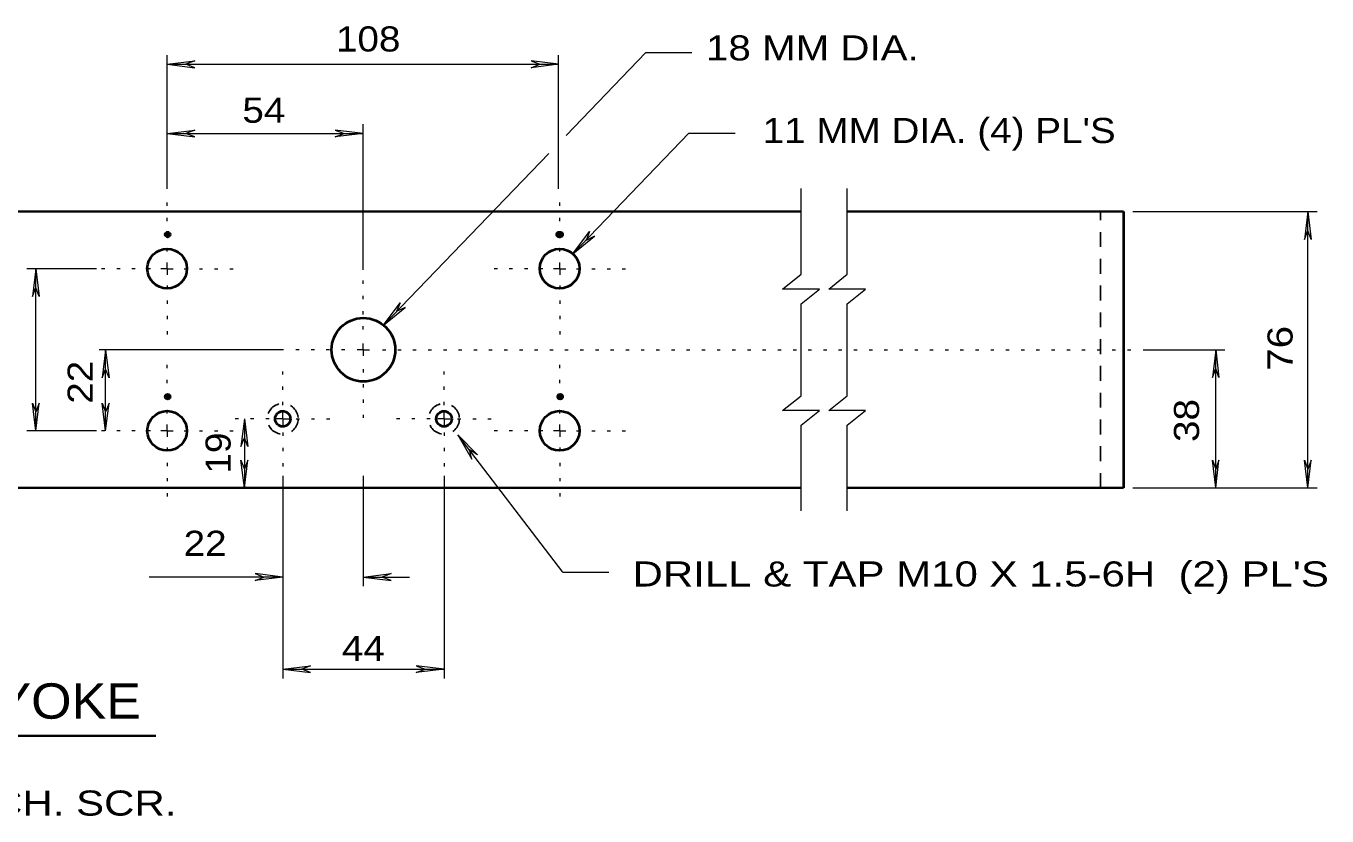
# Model space of a CAD drawing. Extents: x 312583 to 312854, y 144419 to 144597.
# Drawn here: x 312636.96 to 312676.32, y 144504.92 to 144528.83 of the extents above; entities that cross this region are included whole.
import ezdxf
from ezdxf.enums import TextEntityAlignment as Align

# ---------------------------------------------------------------- set-up
doc = ezdxf.new("R2010")
doc.units = 0
doc.header["$LTSCALE"] = 0.3
doc.header["$PDMODE"] = 32
doc.header["$PDSIZE"] = 0.15
doc.linetypes.add('DOTTED', pattern=[1.5, 0.3, -1.2])
doc.linetypes.add('SHORT_DASHED', pattern=[2.7, 1.5, -1.2])
doc.layers.add('1', color=7, linetype='Continuous', lineweight=40)
doc.layers.add('2', color=7, linetype='Continuous', lineweight=13)

msp = doc.modelspace()

# ---------------------------------------------------------------- linework, layer by layer
at = {"layer": '1', "linetype": 'SHORT_DASHED', "lineweight": 25}
msp.add_line((312669.4622, 144514.85), (312669.4622, 144523.2143), dxfattribs=at)
at = {"layer": '1'}
msp.add_line((312670.1599, 144523.2143), (312670.1599, 144514.85), dxfattribs=at)
for centre, radius in [((312641.2245, 144521.4844), 0.5994), ((312653.1009, 144521.4844), 0.5994), ((312647.1627, 144519.0311), 0.9618), ((312641.2245, 144516.5778), 0.5994), ((312644.7233, 144516.9402), 0.2323), ((312649.6021, 144516.9402), 0.2323), ((312653.1009, 144516.5778), 0.5994)]:
    msp.add_circle(centre, radius, dxfattribs=at)
at = {"layer": '1', "linetype": 'SHORT_DASHED', "lineweight": 25}
for centre in [(312644.7233, 144516.9402), (312649.6021, 144516.9402)]:
    msp.add_circle(centre, 0.4647, dxfattribs=at)
at = {"layer": '1'}
for p in [(312641.2412, 144522.5166), (312653.0862, 144522.5166), (312653.1169, 144522.5166), (312641.2412, 144517.61), (312653.1169, 144517.61)]:
    msp.add_point(p, dxfattribs=at)
at = {"layer": '2'}
for p, q in [((312641.2259, 144523.9043), (312641.2259, 144527.9446)), ((312653.0709, 144523.9043), (312653.0709, 144527.9446)), ((312653.2932, 144525.5143), (312655.7082, 144528.0213)), ((312655.7082, 144528.0213), (312657.1036, 144528.0213)), ((312641.2259, 144527.6686), (312642.0616, 144527.7683)), ((312641.2259, 144527.6686), (312653.0709, 144527.6686)), ((312641.2259, 144527.6686), (312642.0616, 144527.5613)), ((312642.0616, 144527.7683), (312641.7932, 144527.6686)), ((312642.0616, 144527.5613), (312641.7932, 144527.6686)), ((312652.2352, 144527.7683), (312652.5036, 144527.6686)), ((312653.0709, 144527.6686), (312652.2352, 144527.7683)), ((312652.2352, 144527.5613), (312652.5036, 144527.6686)), ((312653.0709, 144527.6686), (312652.2352, 144527.5613)), ((312641.2259, 144525.5756), (312642.0616, 144525.6753)), ((312641.2259, 144525.5756), (312647.1522, 144525.5756)), ((312641.2259, 144525.5756), (312642.0616, 144525.4683)), ((312642.0616, 144525.6753), (312641.7932, 144525.5756)), ((312642.0616, 144525.4683), (312641.7932, 144525.5756)), ((312646.3089, 144525.6753), (312646.5772, 144525.5756)), ((312647.1522, 144525.5756), (312646.3089, 144525.6753)), ((312646.3089, 144525.4683), (312646.5772, 144525.5756)), ((312647.1522, 144525.5756), (312646.3089, 144525.4683)), ((312647.1522, 144521.451), (312647.1522, 144525.8516)), ((312653.5002, 144521.934), (312657.0116, 144525.5833)), ((312657.0116, 144525.5833), (312658.4069, 144525.5833)), ((312647.7732, 144519.772), (312652.7719, 144524.97)), ((312670.4436, 144523.2143), (312676.0172, 144523.2143)), ((312675.7412, 144523.2143), (312675.6339, 144522.371)), ((312675.7412, 144514.85), (312675.7412, 144523.2143)), ((312675.7412, 144523.2143), (312675.8409, 144522.371)), ((312653.5002, 144521.934), (312654.0062, 144522.6086)), ((312653.5002, 144521.934), (312654.1596, 144522.463)), ((312654.0062, 144522.6086), (312653.8989, 144522.3403)), ((312654.1596, 144522.463), (312653.8989, 144522.3403)), ((312675.6339, 144522.371), (312675.7412, 144522.6393)), ((312675.8409, 144522.371), (312675.7412, 144522.6393)), ((312641.2259, 144521.4816), (312641.2259, 144521.6733)), ((312653.1016, 144521.4816), (312653.1016, 144521.6733)), ((312639.0869, 144521.4816), (312636.9786, 144521.4816)), ((312637.2546, 144521.4816), (312637.1549, 144520.646)), ((312637.2546, 144516.575), (312637.2546, 144521.4816)), ((312637.2546, 144521.4816), (312637.3542, 144520.646)), ((312641.2259, 144521.4816), (312641.0342, 144521.4816)), ((312641.2259, 144521.4816), (312641.4099, 144521.4816)), ((312641.2259, 144521.4816), (312641.2259, 144521.2976)), ((312653.1016, 144521.4816), (312652.9176, 144521.4816)), ((312653.1016, 144521.4816), (312653.2856, 144521.4816)), ((312653.1016, 144521.4816), (312653.1016, 144521.2976)), ((312637.1549, 144520.646), (312637.2546, 144520.9143)), ((312637.3542, 144520.646), (312637.2546, 144520.9143)), ((312647.7732, 144519.772), (312648.2792, 144520.4543)), ((312648.2792, 144520.4543), (312648.1642, 144520.186)), ((312660.4079, 144519.0283), (312660.4079, 144520.4236)), ((312661.7956, 144519.0283), (312661.7956, 144520.4236)), ((312647.7732, 144519.772), (312648.4249, 144520.3086)), ((312648.4249, 144520.3086), (312648.1642, 144520.186)), ((312647.1599, 144519.0283), (312647.1599, 144519.22)), ((312644.7449, 144519.0283), (312639.1712, 144519.0283)), ((312639.3629, 144519.0206), (312639.2632, 144518.1773)), ((312639.3629, 144516.575), (312639.3629, 144519.0206)), ((312639.3629, 144519.0206), (312639.4702, 144518.1773)), ((312647.1599, 144519.0283), (312646.9759, 144519.0283)), ((312647.1599, 144519.0283), (312647.3516, 144519.0283)), ((312647.1599, 144519.0283), (312647.1599, 144518.8443)), ((312670.7579, 144519.0283), (312673.2266, 144519.0283)), ((312672.9506, 144519.0283), (312672.8509, 144518.1926)), ((312672.9506, 144514.85), (312672.9506, 144519.0283)), ((312672.9506, 144519.0283), (312673.0502, 144518.1926)), ((312639.2632, 144518.1773), (312639.3629, 144518.4456)), ((312639.4702, 144518.1773), (312639.3629, 144518.4456)), ((312672.8509, 144518.1926), (312672.9506, 144518.461)), ((312673.0502, 144518.1926), (312672.9506, 144518.461)), ((312637.1549, 144517.4183), (312637.2546, 144517.15)), ((312637.2546, 144516.575), (312637.1549, 144517.4183)), ((312637.3542, 144517.4183), (312637.2546, 144517.15)), ((312637.2546, 144516.575), (312637.3542, 144517.4183)), ((312639.2632, 144517.4183), (312639.3629, 144517.15)), ((312639.3629, 144516.575), (312639.2632, 144517.4183)), ((312639.4702, 144517.4183), (312639.3629, 144517.15)), ((312639.3629, 144516.575), (312639.4702, 144517.4183)), ((312643.5642, 144516.943), (312643.4569, 144516.0996)), ((312643.5642, 144516.943), (312643.5642, 144514.85)), ((312643.5642, 144516.943), (312643.6639, 144516.0996)), ((312644.7219, 144516.943), (312644.5379, 144516.943)), ((312644.7219, 144516.943), (312644.7219, 144517.127)), ((312644.7219, 144516.943), (312644.9136, 144516.943)), ((312644.7219, 144516.943), (312644.7219, 144516.7513)), ((312649.6056, 144516.943), (312649.4139, 144516.943)), ((312649.6056, 144516.943), (312649.6056, 144517.127)), ((312649.6056, 144516.943), (312649.7896, 144516.943)), ((312649.6056, 144516.943), (312649.6056, 144516.7513)), ((312639.0869, 144516.575), (312636.9786, 144516.575)), ((312641.2259, 144516.575), (312641.0342, 144516.575)), ((312641.2259, 144516.575), (312641.2259, 144516.7666)), ((312641.2259, 144516.575), (312641.4099, 144516.575)), ((312641.2259, 144516.575), (312641.2259, 144516.391)), ((312653.1936, 144512.3046), (312650.0196, 144516.46)), ((312650.0196, 144516.46), (312650.4489, 144515.724)), ((312650.0196, 144516.46), (312650.6176, 144515.8543)), ((312653.1016, 144516.575), (312652.9176, 144516.575)), ((312653.1016, 144516.575), (312653.1016, 144516.7666)), ((312653.1016, 144516.575), (312653.2856, 144516.575)), ((312653.1016, 144516.575), (312653.1016, 144516.391)), ((312660.4079, 144514.1523), (312660.4079, 144516.7436)), ((312661.7956, 144514.1523), (312661.7956, 144516.7436)), ((312643.4569, 144516.0996), (312643.5642, 144516.368)), ((312643.6639, 144516.0996), (312643.5642, 144516.368)), ((312643.4569, 144515.6856), (312643.5642, 144515.4173)), ((312643.5642, 144514.85), (312643.4569, 144515.6856)), ((312643.6639, 144515.6856), (312643.5642, 144515.4173)), ((312643.5642, 144514.85), (312643.6639, 144515.6856)), ((312650.4489, 144515.724), (312650.3722, 144516)), ((312650.6176, 144515.8543), (312650.3722, 144516)), ((312672.8509, 144515.6856), (312672.9506, 144515.4173)), ((312672.9506, 144514.85), (312672.8509, 144515.6856)), ((312673.0502, 144515.6856), (312672.9506, 144515.4173)), ((312672.9506, 144514.85), (312673.0502, 144515.6856)), ((312675.6339, 144515.6856), (312675.7412, 144515.4173)), ((312675.7412, 144514.85), (312675.6339, 144515.6856)), ((312675.8409, 144515.6856), (312675.7412, 144515.4173)), ((312675.7412, 144514.85), (312675.8409, 144515.6856)), ((312644.7219, 144515.218), (312644.7219, 144509.0846)), ((312647.1599, 144515.218), (312647.1599, 144511.8753)), ((312649.6056, 144515.218), (312649.6056, 144509.0846)), ((312670.4436, 144514.85), (312676.0172, 144514.85)), ((312644.7219, 144512.1513), (312640.6816, 144512.1513)), ((312643.8862, 144512.2586), (312644.1546, 144512.1513)), ((312644.7219, 144512.1513), (312643.8862, 144512.2586)), ((312643.8862, 144512.0516), (312644.1546, 144512.1513)), ((312644.7219, 144512.1513), (312643.8862, 144512.0516)), ((312647.1599, 144512.1513), (312648.0032, 144512.2586)), ((312647.1599, 144512.1513), (312648.5552, 144512.1513)), ((312647.1599, 144512.1513), (312648.0032, 144512.0516)), ((312648.0032, 144512.2586), (312647.7349, 144512.1513)), ((312648.0032, 144512.0516), (312647.7349, 144512.1513)), ((312653.1936, 144512.3046), (312654.5889, 144512.3046)), ((312644.7219, 144509.3683), (312645.5652, 144509.468)), ((312644.7219, 144509.3683), (312649.6056, 144509.3683)), ((312644.7219, 144509.3683), (312645.5652, 144509.261)), ((312645.5652, 144509.468), (312645.2969, 144509.3683)), ((312645.5652, 144509.261), (312645.2969, 144509.3683)), ((312648.7622, 144509.468), (312649.0306, 144509.3683)), ((312649.6056, 144509.3683), (312648.7622, 144509.468)), ((312648.7622, 144509.261), (312649.0306, 144509.3683)), ((312649.6056, 144509.3683), (312648.7622, 144509.261))]:
    msp.add_line(p, q, dxfattribs=at)
at = {"layer": '2', "linetype": 'DOTTED'}
for p, q in [((312641.2259, 144522.003), (312641.2259, 144523.6206)), ((312653.1016, 144522.003), (312653.1016, 144523.6206)), ((312640.7199, 144521.4816), (312639.0869, 144521.4816)), ((312641.7396, 144521.4816), (312643.3649, 144521.4816)), ((312647.1599, 144519.6416), (312647.1599, 144521.1673)), ((312652.5956, 144521.4816), (312650.9626, 144521.4816)), ((312653.6152, 144521.4816), (312655.2406, 144521.4816)), ((312641.2259, 144520.9756), (312641.2259, 144519.3426)), ((312653.1016, 144520.9756), (312653.1016, 144519.3426)), ((312646.6002, 144519.0283), (312645.0209, 144519.0283)), ((312647.7426, 144519.0283), (312670.4742, 144519.0283)), ((312641.2259, 144517.0963), (312641.2259, 144518.714)), ((312647.1599, 144518.4456), (312647.1599, 144516.8893)), ((312653.1016, 144517.0963), (312653.1016, 144518.714)), ((312644.7219, 144517.357), (312644.7219, 144518.3843)), ((312649.6056, 144517.357), (312649.6056, 144518.3843)), ((312644.3079, 144516.943), (312643.2806, 144516.943)), ((312645.1282, 144516.943), (312646.1632, 144516.943)), ((312649.1839, 144516.943), (312648.1642, 144516.943)), ((312650.0119, 144516.943), (312651.0469, 144516.943)), ((312640.7199, 144516.575), (312639.0869, 144516.575)), ((312641.7396, 144516.575), (312643.3649, 144516.575)), ((312644.7219, 144516.5213), (312644.7219, 144515.5016)), ((312649.6056, 144516.5213), (312649.6056, 144515.5016)), ((312652.5956, 144516.575), (312650.9626, 144516.575)), ((312653.6152, 144516.575), (312655.2406, 144516.575)), ((312641.2259, 144516.069), (312641.2259, 144514.436)), ((312653.1016, 144516.069), (312653.1016, 144514.436))]:
    msp.add_line(p, q, dxfattribs=at)
at = {"layer": '2', "lineweight": 35}
for p, q in [((312633.9196, 144523.2143), (312647.1599, 144523.2143)), ((312660.4079, 144523.2143), (312647.1599, 144523.2143)), ((312670.1599, 144523.2143), (312661.7956, 144523.2143)), ((312633.9196, 144514.85), (312647.1599, 144514.85)), ((312660.4079, 144514.85), (312647.1599, 144514.85)), ((312670.1599, 144514.85), (312661.7956, 144514.85)), ((312619.3293, 144507.3524), (312640.8849, 144507.3524))]:
    msp.add_line(p, q, dxfattribs=at)
at = {"layer": '2'}
for points in [[(312660.4079, 144520.4236), (312660.9599, 144520.8683), (312659.8482, 144520.8683), (312660.4079, 144521.3206), (312660.4079, 144523.912)], [(312661.7956, 144520.4236), (312662.3552, 144520.8683), (312661.2436, 144520.8683), (312661.7956, 144521.3206), (312661.7956, 144523.912)], [(312660.4079, 144516.7436), (312660.9599, 144517.1883), (312659.8482, 144517.1883), (312660.4079, 144517.6406), (312660.4079, 144519.0283)], [(312661.7956, 144516.7436), (312662.3552, 144517.1883), (312661.2436, 144517.1883), (312661.7956, 144517.6406), (312661.7956, 144519.0283)]]:
    msp.add_lwpolyline(points, dxfattribs=at)

# ---------------------------------------------------------------- texts
for s, width, p in [('108 ', 1.15, (312646.3332, 144528.0549)), ('18 MM DIA.', 1.2, (312657.5286, 144527.7841)), ('54 ', 1.15, (312643.5016, 144525.8986)), ("11 MM DIA. (4) PL'S", 1.15, (312659.2447, 144525.2848)), ('22 ', 1.15, (312641.7251, 144512.7935)), ("DRILL & TAP M10 X 1.5-6H  (2) PL'S", 1.25, (312655.3057, 144511.8662)), ('44 ', 1.15, (312646.5136, 144509.6127)), ('M10 X 1.5 x 32 HEX HD. MACH. SCR.', 1.25, (312619.6206, 144504.9329))]:
    msp.add_text(s, height=0.76, dxfattribs=dict(at, width=width)).set_placement(p)
for s, width, p in [('76 ', 1.2, (312675.277, 144518.3942)), ('22 ', 1.15, (312638.9725, 144517.3958)), ('38 ', 1.15, (312672.4471, 144516.2387)), ('19 ', 1.1, (312643.1466, 144515.282))]:
    msp.add_text(s, height=0.76, rotation=90, dxfattribs=dict(at, width=width)).set_placement(p)
at = {"layer": '2', "width": 1.1}
msp.add_text('FURNISH WITH EACH YOKE', height=1.07, dxfattribs=at).set_placement((312629.8964, 144507.8661), align=Align.CENTER)

doc.saveas('drawing.dxf')
